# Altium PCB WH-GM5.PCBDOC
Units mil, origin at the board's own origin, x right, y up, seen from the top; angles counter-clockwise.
Board outline 1167.01 x 1186.42 mil, 2 copper layers (Top Layer, Bottom Layer); 7 components, 4 nets, 81 pads, 0 vias.
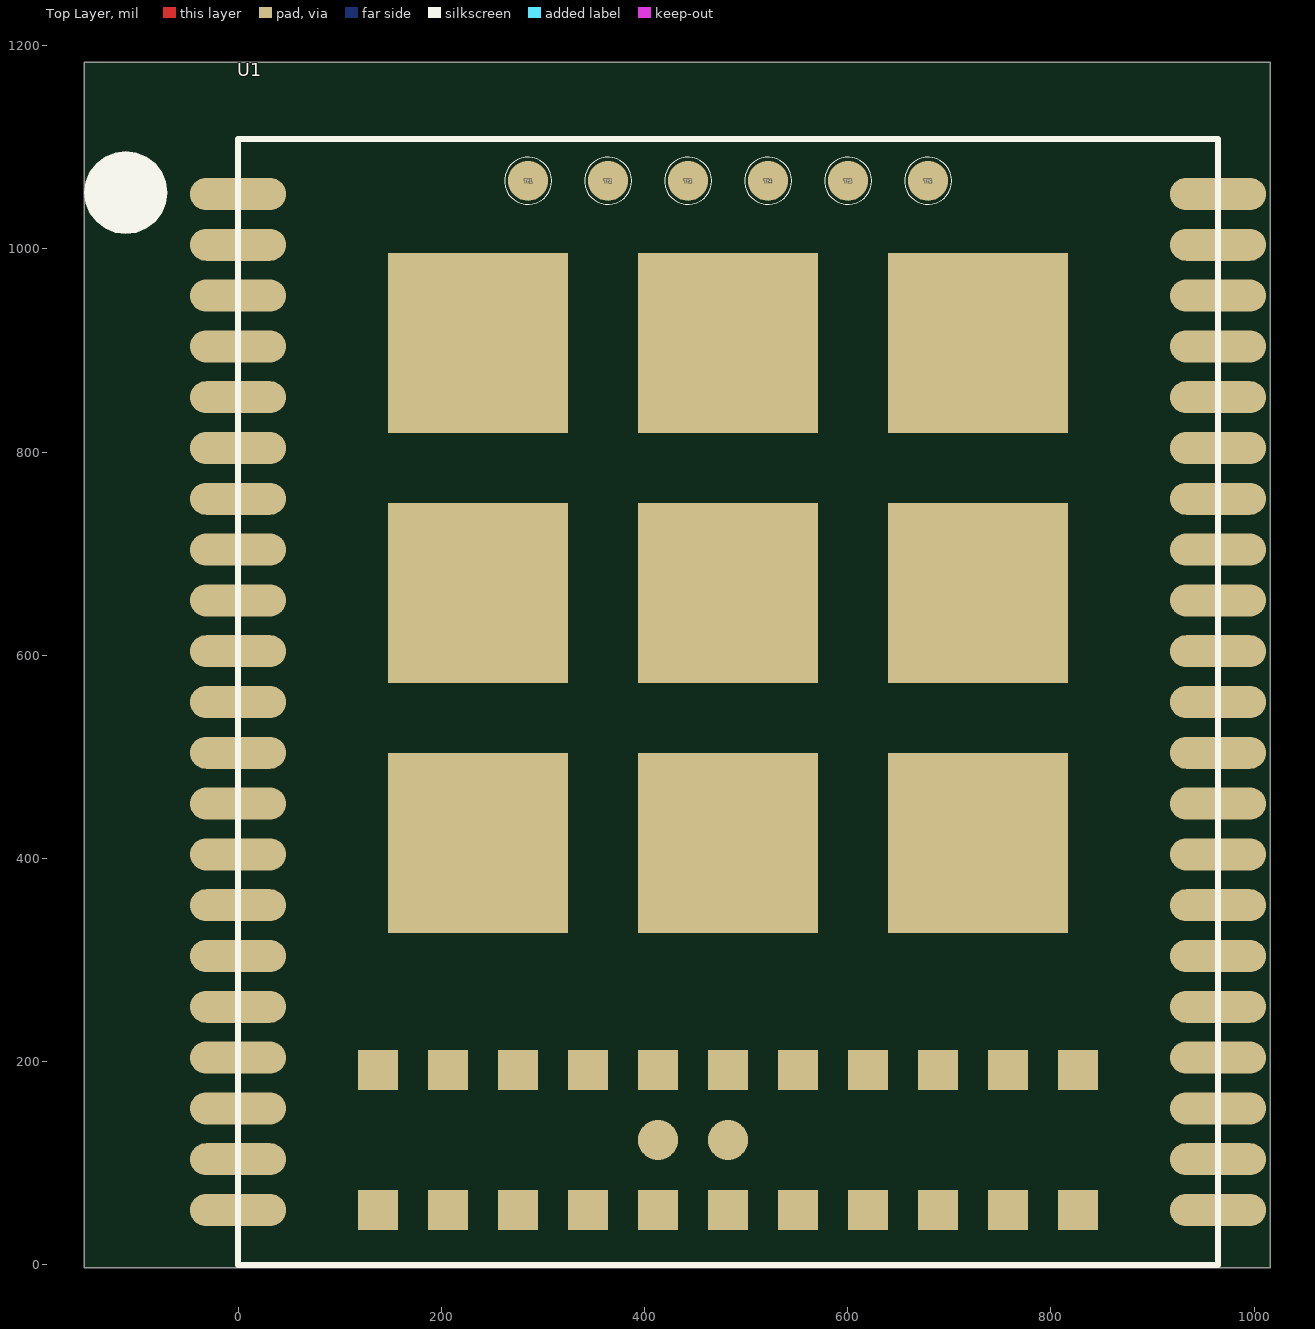
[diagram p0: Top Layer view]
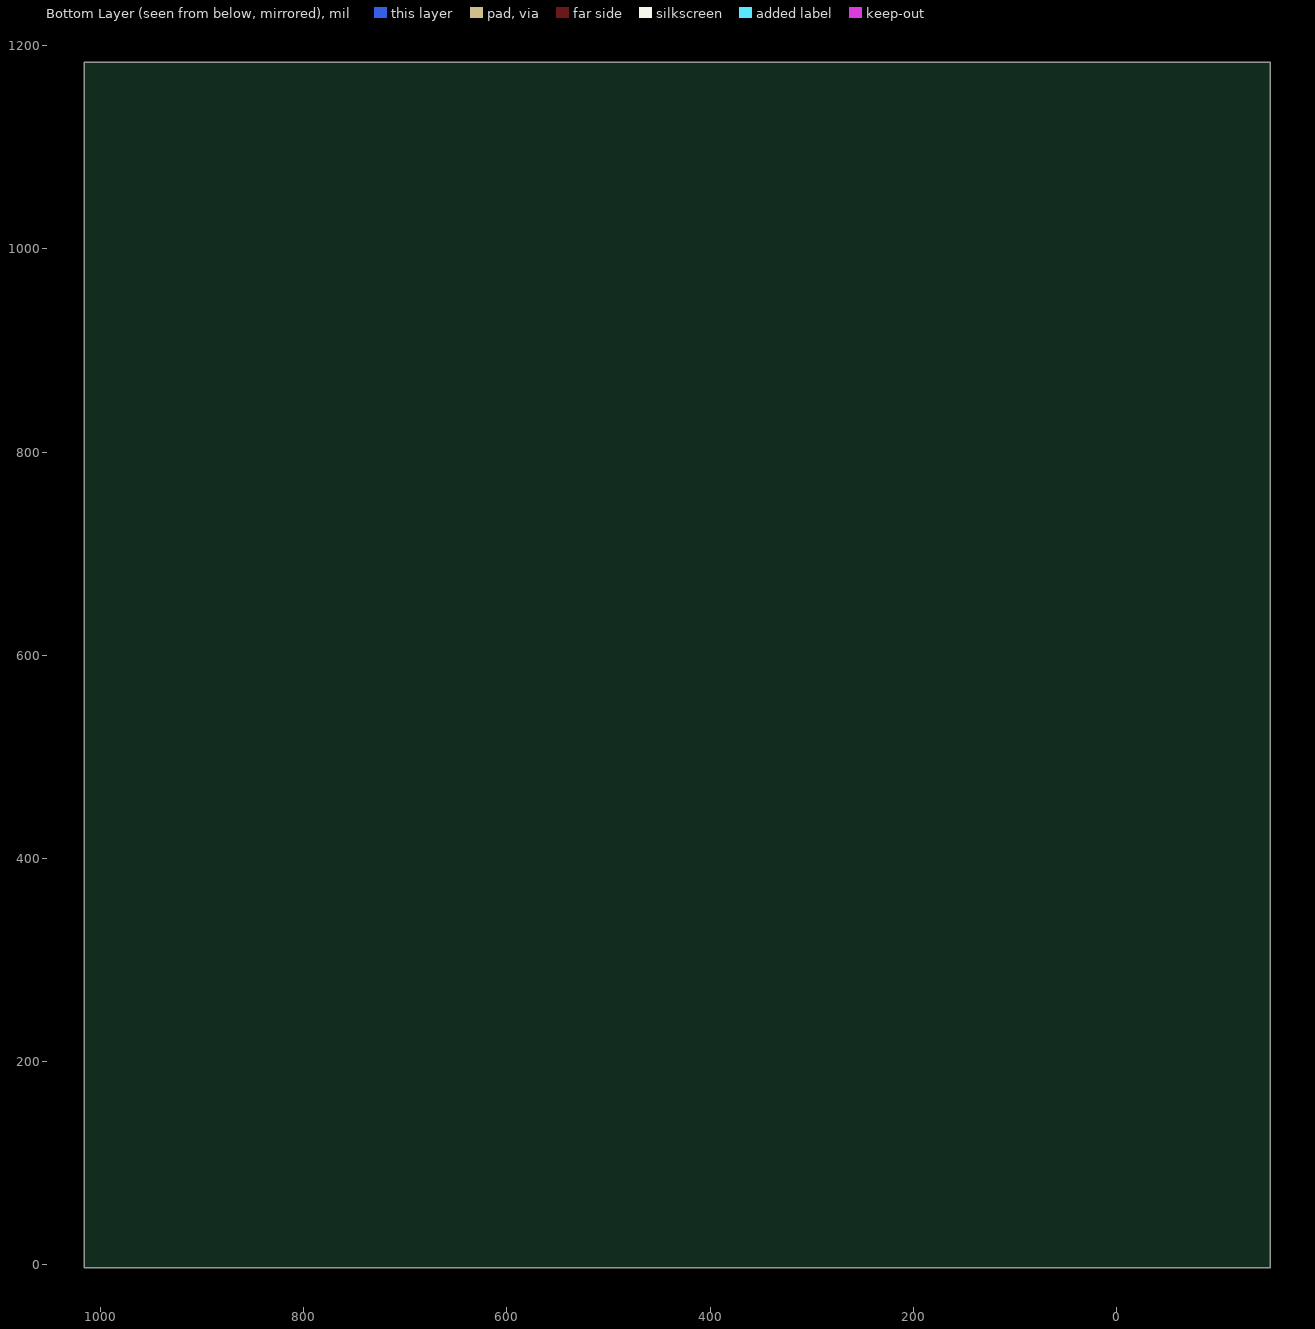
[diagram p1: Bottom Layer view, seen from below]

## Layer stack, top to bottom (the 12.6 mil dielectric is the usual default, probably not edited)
Top Layer: signal copper 1.4
Dielectric: dielectric 12.6, FR-4, Dk 4.8
Bottom Layer: signal copper 1.4

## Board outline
-151.2,-2.95 1015.81,-2.95 1015.81,1183.47 -151.2,1183.47

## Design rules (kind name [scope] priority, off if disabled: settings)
Clearance "'Default' PADS rule_18" [All] p1: gap=6
Clearance "'Default' PADS rule_15" [IsVia vs IsVia] p2: gap=6
ComponentClearance "'Default' PADS rule_12" [All] p1: gap=6 collisioncheckmode=3 verticalgap=10 showdistances=FALSE
FlightTimeFalling "'Default' PADS rule_10" [All] p1: maximum=10.00
FlightTimeRising "'Default' PADS rule_9" [All] p1: maximum=10.00
Length "'Default' PADS rule_5" [All] p1: maxlimit=50000 minlimit=0
MatchedLengths "'Default' PADS rule_11" [InNetClass('All Nets')] p1: tolerance=200 checknetsindiffpair=TRUE checkdiffpairvsdiffpair=TRUE checkothers=TRUE
MaxMinImpedance "'Default' PADS rule_8" [All] p1: minimum=50.00 maximum=150.0
ParallelSegment "'Default' PADS rule_7" [All] p1: limit=1000 gap=200
ParallelSegment "'Default' PADS rule_6" [All] p2: limit=1000 gap=200
PlaneClearance "'Default' PADS rule_14" [All] p1: clearance=6
PlaneConnect "Power Plane Connect Style - from global settings" [All] p1: planeconnectstyle=Relief reliefexpansion=20 reliefentries=2 reliefconductorwidth=15.75 reliefairgap=10
PolygonConnect [All] p1: connectstyle=Relief reliefconductorwidth=10 reliefentries=4 polygonreliefangle="90 Angle"
RoutingLayers "'Default' PADS rule_3" [All] p1: top layer_v5=FALSE bottom layer_v5=FALSE
RoutingPriority "'Default' PADS rule_2" [All] p1: routingpriority=3
RoutingTopology "'Default' PADS rule" [All] p1: topology=Shortest
RoutingVias "'Default' PADS rule_4" [All] p1: holewidth=37 width=55 viastyle="Through Hole" minholewidth=37 minwidth=55 maxholewidth=37 maxwidth=55
SMDToCorner "'Default' PADS rule_16" [All] p1: distance=60000
SMDToPlane "'Default' PADS rule_17" [All] p1: distance=60000
SilkscreenOverComponentPads [All] p1: minsilkscreentomaskgap=10
SolderMaskExpansion [All] p1: expansion=4
Width "'Default' PADS rule_13" [All] p1: maxlimit=12 minlimit=12 preferedwidth=12
21 further rules are at their usual default settings.

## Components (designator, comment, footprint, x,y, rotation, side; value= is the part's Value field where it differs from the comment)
TP1 "TP_C150" TP_C150 285.43,1066.93 r0 top
TP2 "TP_C150" TP_C150 364.17,1066.93 r0 top
TP3 "TP_C150" TP_C150 442.91,1066.93 r0 top
TP4 "TP_C150" TP_C150 521.65,1066.93 r0 top
TP5 "TP_C150" TP_C150 600.39,1066.93 r0 top
TP6 "TP_C150" TP_C150 679.13,1066.93 r0 top
U1 "WH-GM5" WH-GM5 0,0 r0 top

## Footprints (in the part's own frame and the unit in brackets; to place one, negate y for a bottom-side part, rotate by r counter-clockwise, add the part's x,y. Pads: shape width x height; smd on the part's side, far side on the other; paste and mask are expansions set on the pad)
TP_C150 [mm]
  round 1 smd mask+0.05: 1(0,0)
  silkscreen extent -0.59,-0.59 0.59,0.59
WH-GM5 [mm]
  oval 2.4x0.8 smd mask+0.025: 1(0,26.77) 2(0,25.5) 3(0,24.23) 4(0,22.96) 5(0,21.69) 6(0,20.42) 7(0,19.15) 8(0,17.88) 9(0,16.61) 10(0,15.34) 11(0,14.07) 12(0,12.8) 13(0,11.53) 14(0,10.26) 15(0,8.99) 16(0,7.72) 17(0,6.45) 18(0,5.18) 19(0,3.91) 20(0,2.64) 21(0,1.37) 22(24.5,1.37) 23(24.5,2.64) 24(24.5,3.91) 25(24.5,5.18) 26(24.5,6.45) 27(24.5,7.72) 28(24.5,8.99) 29(24.5,10.26) 30(24.5,11.53) 31(24.5,12.8) 32(24.5,14.07) 33(24.5,15.34) 34(24.5,16.61) 35(24.5,17.88) 36(24.5,19.15) 37(24.5,20.42) 38(24.5,21.69) 39(24.5,22.96) 40(24.5,24.23) 41(24.5,25.5) 42(24.5,26.77)
  rect 1x1 smd mask+0.025: 43(3.5,1.37) 44(5.25,1.37) 45(7,1.37) 46(8.75,1.37) 47(10.5,1.37) 48(12.25,1.37) 49(14,1.37) 50(15.75,1.37) 51(17.5,1.37) 52(19.25,1.37) 53(21,1.37) 54(3.5,4.87) 66(5.25,4.87) 67(7,4.87) 68(8.75,4.87) 69(10.5,4.87) 70(12.25,4.87) 71(14,4.87) 72(15.75,4.87) 73(17.5,4.87) 74(19.25,4.87) 75(21,4.87)
  rect 4.5x4.5 smd mask+0.025: 55(6,23.04) 56(12.25,23.04) 57(18.5,23.04) 58(18.5,16.79) 59(12.25,16.79) 60(6,16.79) 61(6,10.54) 62(12.25,10.54) 63(18.5,10.54)
  round 1 smd mask+0.025: 64(10.5,3.12) 65(12.25,3.12)
  silkscreen extent -3.84,0 24.5,28.14

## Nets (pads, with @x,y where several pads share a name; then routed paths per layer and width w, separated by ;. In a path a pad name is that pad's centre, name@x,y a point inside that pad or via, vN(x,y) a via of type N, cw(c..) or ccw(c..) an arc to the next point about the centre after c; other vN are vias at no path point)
GND: U1.3 U1.4 U1.17 U1.39 U1.40 U1.42 U1.55 U1.56 U1.57 U1.58 U1.59 U1.60 U1.61 U1.62 U1.63 U1.65 U1.73 U1.74 U1.75
GPIO20: U1.51 U1.71
GPIO21: U1.52 U1.72
VDD_3V8: U1.1 U1.2
pads on no net: TP1.1 TP2.1 TP3.1 TP4.1 TP5.1 TP6.1 U1.5 U1.6 U1.7 U1.8 U1.9 U1.10 U1.11 U1.12 U1.13 U1.14 U1.15 U1.16 U1.18 U1.19 U1.20 U1.21 U1.22 U1.23 U1.24 U1.25 U1.26 U1.27 U1.28 U1.29 U1.30 U1.31 U1.32 U1.33 U1.34 U1.35 U1.36 U1.37 U1.38 U1.41 U1.43 U1.44 U1.45 U1.46 U1.47 U1.48 U1.49 U1.50 U1.53 U1.54 U1.64 U1.66 U1.67 U1.68 U1.69 U1.70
